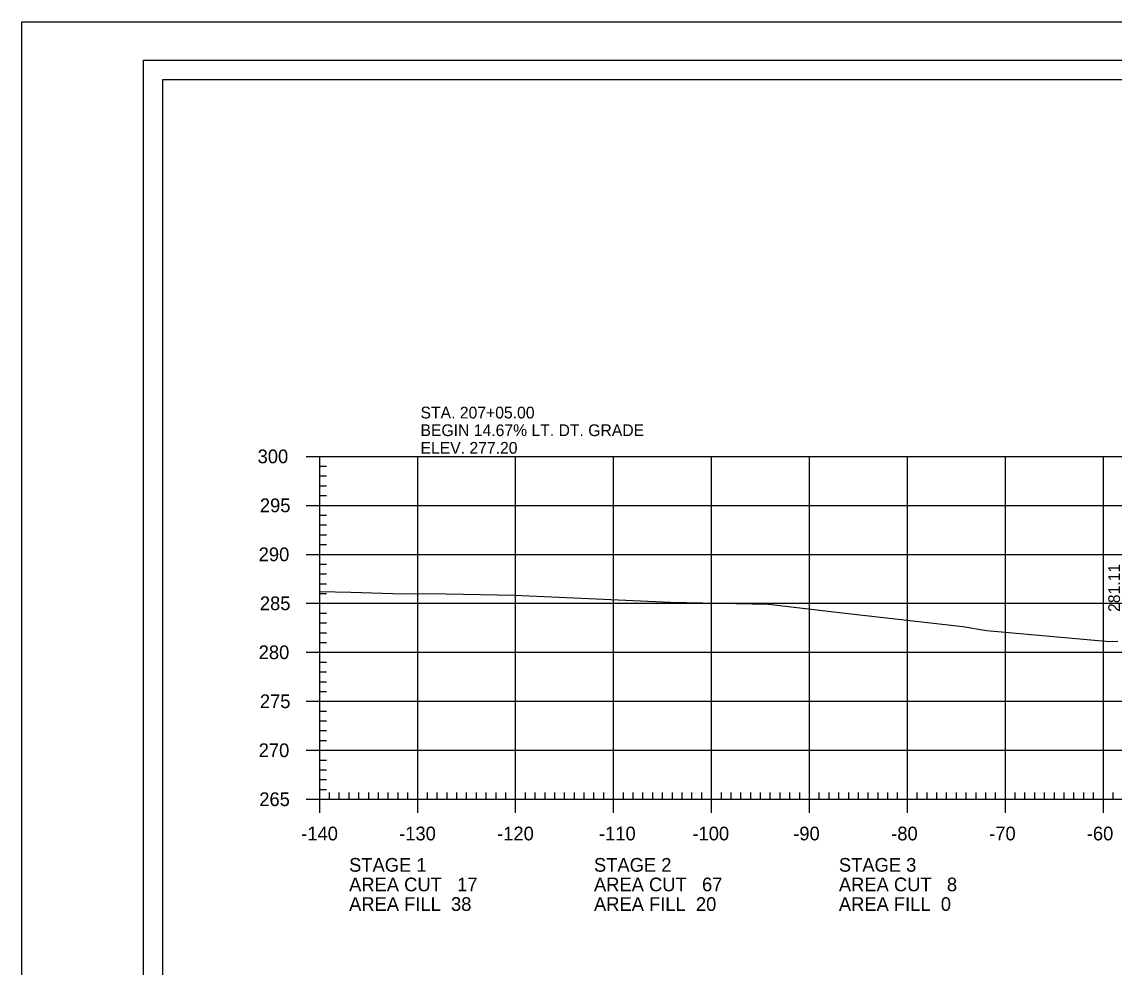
# Model space of a CAD drawing. Extents: x 1368713 to 1370673, y 380279 to 380950.
# Drawn here: x 1370339.2 to 1370450.7, y 380640.6 to 380737.1 of the extents above; entities that cross this region are included whole.
import ezdxf

# ---------------------------------------------------------------- set-up
doc = ezdxf.new("R2010")
doc.units = 0
for name, color, linetype in [('Notes', 7, 'Continuous'), ('R_Axis', 7, 'Continuous'), ('R_Axis Annot', 7, 'Continuous'), ('R_Border', 7, 'Continuous'), ('R_Exist Surface', 7, 'Continuous'), ('R_Grid', 7, 'Continuous'), ('R_No Plot', 7, 'Continuous'), ('R_Xsect Elev', 7, 'Continuous')]:
    doc.layers.add(name, color=color, linetype=linetype)

msp = doc.modelspace()

# ---------------------------------------------------------------- linework, layer by layer
at = {"layer": 'R_Axis'}
for p, q in [((1370368.23, 380692.75), (1370371.03, 380692.75)), ((1370369.63, 380657.75), (1370369.63, 380692.75)), ((1370369.63, 380691.75), (1370370.33, 380691.75)), ((1370369.63, 380690.75), (1370370.33, 380690.75)), ((1370369.63, 380689.75), (1370370.33, 380689.75)), ((1370369.63, 380688.75), (1370370.33, 380688.75)), ((1370368.23, 380687.75), (1370371.03, 380687.75)), ((1370369.63, 380686.75), (1370370.33, 380686.75)), ((1370369.63, 380685.75), (1370370.33, 380685.75)), ((1370369.63, 380684.75), (1370370.33, 380684.75)), ((1370369.63, 380683.75), (1370370.33, 380683.75)), ((1370368.23, 380682.75), (1370371.03, 380682.75)), ((1370369.63, 380681.75), (1370370.33, 380681.75)), ((1370369.63, 380680.75), (1370370.33, 380680.75)), ((1370369.63, 380679.75), (1370370.33, 380679.75)), ((1370369.63, 380678.75), (1370370.33, 380678.75)), ((1370368.23, 380677.75), (1370371.03, 380677.75)), ((1370369.63, 380676.75), (1370370.33, 380676.75)), ((1370369.63, 380675.75), (1370370.33, 380675.75)), ((1370369.63, 380674.75), (1370370.33, 380674.75)), ((1370369.63, 380673.75), (1370370.33, 380673.75)), ((1370368.23, 380672.75), (1370371.03, 380672.75)), ((1370369.63, 380671.75), (1370370.33, 380671.75)), ((1370369.63, 380670.75), (1370370.33, 380670.75)), ((1370369.63, 380669.75), (1370370.33, 380669.75)), ((1370369.63, 380668.75), (1370370.33, 380668.75)), ((1370368.23, 380667.75), (1370371.03, 380667.75)), ((1370369.63, 380666.75), (1370370.33, 380666.75)), ((1370369.63, 380665.75), (1370370.33, 380665.75)), ((1370369.63, 380664.75), (1370370.33, 380664.75)), ((1370369.63, 380663.75), (1370370.33, 380663.75)), ((1370368.23, 380662.75), (1370371.03, 380662.75)), ((1370369.63, 380661.75), (1370370.33, 380661.75)), ((1370369.63, 380660.75), (1370370.33, 380660.75)), ((1370369.63, 380659.75), (1370370.33, 380659.75)), ((1370369.63, 380656.35), (1370369.63, 380659.15)), ((1370369.63, 380658.75), (1370370.33, 380658.75)), ((1370370.63, 380657.75), (1370370.63, 380658.45)), ((1370371.63, 380657.75), (1370371.63, 380658.45)), ((1370372.63, 380657.75), (1370372.63, 380658.45)), ((1370373.63, 380657.75), (1370373.63, 380658.45)), ((1370374.63, 380657.75), (1370374.63, 380658.45)), ((1370375.63, 380657.75), (1370375.63, 380658.45)), ((1370376.63, 380657.75), (1370376.63, 380658.45)), ((1370377.63, 380657.75), (1370377.63, 380658.45)), ((1370378.63, 380657.75), (1370378.63, 380658.45)), ((1370379.63, 380656.35), (1370379.63, 380659.15)), ((1370380.63, 380657.75), (1370380.63, 380658.45)), ((1370381.63, 380657.75), (1370381.63, 380658.45)), ((1370382.63, 380657.75), (1370382.63, 380658.45)), ((1370383.63, 380657.75), (1370383.63, 380658.45)), ((1370384.63, 380657.75), (1370384.63, 380658.45)), ((1370385.63, 380657.75), (1370385.63, 380658.45)), ((1370386.63, 380657.75), (1370386.63, 380658.45)), ((1370387.63, 380657.75), (1370387.63, 380658.45)), ((1370388.63, 380657.75), (1370388.63, 380658.45)), ((1370389.63, 380656.35), (1370389.63, 380659.15)), ((1370390.63, 380657.75), (1370390.63, 380658.45)), ((1370391.63, 380657.75), (1370391.63, 380658.45)), ((1370392.63, 380657.75), (1370392.63, 380658.45)), ((1370393.63, 380657.75), (1370393.63, 380658.45)), ((1370394.63, 380657.75), (1370394.63, 380658.45)), ((1370395.63, 380657.75), (1370395.63, 380658.45)), ((1370396.63, 380657.75), (1370396.63, 380658.45)), ((1370397.63, 380657.75), (1370397.63, 380658.45)), ((1370398.63, 380657.75), (1370398.63, 380658.45)), ((1370399.63, 380656.35), (1370399.63, 380659.15)), ((1370400.63, 380657.75), (1370400.63, 380658.45)), ((1370401.63, 380657.75), (1370401.63, 380658.45)), ((1370402.63, 380657.75), (1370402.63, 380658.45)), ((1370403.63, 380657.75), (1370403.63, 380658.45)), ((1370404.63, 380657.75), (1370404.63, 380658.45)), ((1370405.63, 380657.75), (1370405.63, 380658.45)), ((1370406.63, 380657.75), (1370406.63, 380658.45)), ((1370407.63, 380657.75), (1370407.63, 380658.45)), ((1370408.63, 380657.75), (1370408.63, 380658.45)), ((1370409.63, 380656.35), (1370409.63, 380659.15)), ((1370410.63, 380657.75), (1370410.63, 380658.45)), ((1370411.63, 380657.75), (1370411.63, 380658.45)), ((1370412.63, 380657.75), (1370412.63, 380658.45)), ((1370413.63, 380657.75), (1370413.63, 380658.45)), ((1370414.63, 380657.75), (1370414.63, 380658.45)), ((1370415.63, 380657.75), (1370415.63, 380658.45)), ((1370416.63, 380657.75), (1370416.63, 380658.45)), ((1370417.63, 380657.75), (1370417.63, 380658.45)), ((1370418.63, 380657.75), (1370418.63, 380658.45)), ((1370419.63, 380656.35), (1370419.63, 380659.15)), ((1370420.63, 380657.75), (1370420.63, 380658.45)), ((1370421.63, 380657.75), (1370421.63, 380658.45)), ((1370422.63, 380657.75), (1370422.63, 380658.45)), ((1370423.63, 380657.75), (1370423.63, 380658.45)), ((1370424.63, 380657.75), (1370424.63, 380658.45)), ((1370425.63, 380657.75), (1370425.63, 380658.45)), ((1370426.63, 380657.75), (1370426.63, 380658.45)), ((1370427.63, 380657.75), (1370427.63, 380658.45)), ((1370428.63, 380657.75), (1370428.63, 380658.45)), ((1370429.63, 380656.35), (1370429.63, 380659.15)), ((1370430.63, 380657.75), (1370430.63, 380658.45)), ((1370431.63, 380657.75), (1370431.63, 380658.45)), ((1370432.63, 380657.75), (1370432.63, 380658.45)), ((1370433.63, 380657.75), (1370433.63, 380658.45)), ((1370434.63, 380657.75), (1370434.63, 380658.45)), ((1370435.63, 380657.75), (1370435.63, 380658.45)), ((1370436.63, 380657.75), (1370436.63, 380658.45)), ((1370437.63, 380657.75), (1370437.63, 380658.45)), ((1370438.63, 380657.75), (1370438.63, 380658.45)), ((1370439.63, 380656.35), (1370439.63, 380659.15)), ((1370440.63, 380657.75), (1370440.63, 380658.45)), ((1370441.63, 380657.75), (1370441.63, 380658.45)), ((1370442.63, 380657.75), (1370442.63, 380658.45)), ((1370443.63, 380657.75), (1370443.63, 380658.45)), ((1370444.63, 380657.75), (1370444.63, 380658.45)), ((1370445.63, 380657.75), (1370445.63, 380658.45)), ((1370446.63, 380657.75), (1370446.63, 380658.45)), ((1370447.63, 380657.75), (1370447.63, 380658.45)), ((1370448.63, 380657.75), (1370448.63, 380658.45)), ((1370449.63, 380656.35), (1370449.63, 380659.15)), ((1370450.63, 380657.75), (1370450.63, 380658.45)), ((1370368.23, 380657.75), (1370371.03, 380657.75)), ((1370369.63, 380657.75), (1370649.63, 380657.75))]:
    msp.add_line(p, q, dxfattribs=at)
at = {"layer": 'R_Border'}
for p, q in [((1370351.63, 380733.21), (1370667.81, 380733.21)), ((1370351.63, 380527.75), (1370351.63, 380733.21))]:
    msp.add_line(p, q, dxfattribs=at)
at = {"layer": 'R_Exist Surface'}
msp.add_lwpolyline([(1370369.63, 380678.94), (1370372.82, 380678.89), (1370378.19, 380678.72), (1370380.81, 380678.74), (1370389.5, 380678.58), (1370405.42, 380677.86), (1370415.46, 380677.66), (1370423.57, 380676.72), (1370435.29, 380675.4), (1370437.71, 380674.97), (1370450.25, 380673.85), (1370451.1, 380673.87)], dxfattribs=at)
at = {"layer": 'R_Grid'}
for p, q in [((1370369.63, 380692.75), (1370649.63, 380692.75)), ((1370369.63, 380657.75), (1370369.63, 380692.75)), ((1370379.63, 380657.75), (1370379.63, 380692.75)), ((1370389.63, 380657.75), (1370389.63, 380692.75)), ((1370399.63, 380657.75), (1370399.63, 380692.75)), ((1370409.63, 380657.75), (1370409.63, 380692.75)), ((1370419.63, 380657.75), (1370419.63, 380692.75)), ((1370429.63, 380657.75), (1370429.63, 380692.75)), ((1370439.63, 380657.75), (1370439.63, 380692.75)), ((1370449.63, 380657.75), (1370449.63, 380692.75)), ((1370369.63, 380687.75), (1370649.63, 380687.75)), ((1370369.63, 380682.75), (1370649.63, 380682.75)), ((1370369.63, 380677.75), (1370649.63, 380677.75)), ((1370369.63, 380672.75), (1370649.63, 380672.75)), ((1370369.63, 380667.75), (1370649.63, 380667.75)), ((1370369.63, 380662.75), (1370649.63, 380662.75)), ((1370369.63, 380657.75), (1370649.63, 380657.75))]:
    msp.add_line(p, q, dxfattribs=at)
at = {"layer": 'R_No Plot'}
for points in [[(1370339.22, 380737.11), (1370672.56, 380737.11), (1370672.56, 380523.77), (1370339.22, 380523.77)], [(1370665.81, 380632.48), (1370353.63, 380632.48), (1370353.63, 380731.21), (1370603.17, 380731.21), (1370603.17, 380721.33), (1370620.71, 380721.33), (1370644.81, 380721.33), (1370644.81, 380699), (1370665.81, 380699)], [(1370353.63, 380731.21), (1370603.17, 380731.21), (1370603.17, 380721.33), (1370620.71, 380721.33), (1370644.81, 380721.33), (1370644.81, 380699), (1370665.81, 380699), (1370665.81, 380529.75), (1370353.63, 380529.75)]]:
    msp.add_lwpolyline(points, close=True, dxfattribs=at)

# ---------------------------------------------------------------- texts
at = {"layer": 'Notes'}
for s, p in [('STA. 207+05.00', (1370379.92, 380696.62)), ('BEGIN 14.67% LT. DT. GRADE', (1370379.92, 380694.82)), ('ELEV. 277.20', (1370379.92, 380693.02))]:
    msp.add_text(s, height=1.2, dxfattribs=at).set_placement(p)
at = {"layer": 'R_Axis Annot'}
for s, p in [('300', (1370363.29, 380692.05)), ('295', (1370363.52, 380687.05)), ('290', (1370363.4, 380682.05)), ('285', (1370363.52, 380677.05)), ('280', (1370363.4, 380672.05)), ('275', (1370363.52, 380667.05)), ('270', (1370363.4, 380662.05)), ('265', (1370363.46, 380657.05)), ('-140', (1370367.74, 380653.55)), ('-130', (1370377.74, 380653.55)), ('-120', (1370387.74, 380653.55)), ('-110', (1370398.14, 380653.55)), ('-100', (1370407.68, 380653.55)), ('-90', (1370417.97, 380653.55)), ('-80', (1370427.97, 380653.55)), ('-70', (1370437.97, 380653.55)), ('-60', (1370447.94, 380653.55)), ('STAGE 1', (1370372.63, 380650.35)), ('STAGE 2', (1370397.63, 380650.35)), ('STAGE 3', (1370422.63, 380650.35)), ('AREA CUT   17', (1370372.63, 380648.35)), ('AREA CUT   67', (1370397.63, 380648.35)), ('AREA CUT   8', (1370422.63, 380648.35)), ('AREA FILL  38', (1370372.63, 380646.35)), ('AREA FILL  20', (1370397.63, 380646.35)), ('AREA FILL  0', (1370422.63, 380646.35))]:
    msp.add_text(s, height=1.4, dxfattribs=at).set_placement(p)
at = {"layer": 'R_Xsect Elev'}
msp.add_text('281.11', height=1.2, rotation=90, dxfattribs=at).set_placement((1370451.33, 380676.87))

doc.saveas('drawing.dxf')
